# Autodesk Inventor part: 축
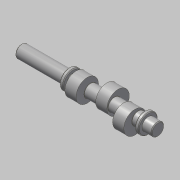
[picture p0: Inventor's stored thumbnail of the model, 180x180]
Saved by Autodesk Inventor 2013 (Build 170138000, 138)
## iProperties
Company: 한국ATC센터
Created: 2014-08
Part Number: 축
Document SubType Name: Modeling
Designer: mdu
Density: 7.86 g/cm^3
Material: 강철, 연강
Mass: 516.584 g
Surface Area: 162.516 cm^2
Volume: 65.7231 cm^3
Author: mdu
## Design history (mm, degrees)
sketch "스케치1"
  geometry: L1 (-91.5, 0)-(91.5, 0); L2 (-91.5, 0)-(-91.5, 8.5); L3 (-91.5, 8.5)-(-27.5, 8.5); L4 (-27.5, 8.5)-(-27.5, 13); L5 (-27.5, 13)-(-22.5, 13); L6 (-22.5, 13)-(-22.5, 8.5); L7 (-22.5, 8.5)-(73.5, 8.5); L8 (73.5, 8.5)-(73.5, 13); L9 (73.5, 13)-(78.5, 13); L10 (78.5, 13)-(78.5, 8.5); L11 (78.5, 8.5)-(91.5, 8.5); L12 (91.5, 8.5)-(91.5, 0); 2 further points
  constraints: 24 end point, 5 parallel, 1 coincident, 1 horizontal, 1 midpoint, 1 perpendicular
  dimensions: "d0" = 183 distance of L1.start L1.end (derived); "d2" = 17 diameter of L3 L1; "d3" = 26 diameter of L5 L1; "d4" = 17 diameter of L7 L1; "d5" = 26 diameter of L9 L1; "d6" = 17 diameter of L11 L1; "d7" = 5 distance of L8.end L9.end; "d8" = 5 distance of L4.end L5.end; "d10" = 64 distance of L2.end L3.end; "d11" = 13 distance of L10.end L11.end; "d35" = 96 distance between parallel lines of L8 L6
revolve "회전1" sketch "스케치1" stored, may be unused: angle "d12" = 90 deg
node "작업 평면7"
sketch "스케치6"
  geometry: C1 r 15 at (0, 5); 1 further point
  constraints: 1 centre point, 1 vertical alignment
  dimensions: "d37" = 30 diameter of C1; "d38" = 5 distance of C1.centre point (0, 0)
extrude "돌출4" join sketch "스케치6" stored distance "d33" = 15; taper "d34" = 0 deg
node "작업 평면8"
sketch "스케치7"
  geometry: L1 (0, 0)-(-6.5, -11.258); L2 (0, 0)-(13, 0); C1 r 15 at (-2.5, -4.33); A1 r 13 centre (0, 0) between (-6.5, -11.258) and (13, 0) reference; 1 further point
  constraints: 4 end point, 2 point on circle, 1 centre point, 1 horizontal, 1 point on line
  dimensions: "d40" = 120 deg angle of L1 L2; "d41" = 30 diameter of C1; "d42" = 5 distance of point (0, 0) C1.centre
extrude "돌출5" join sketch "스케치7" stored distance "d43" = 15; taper "d44" = 0 deg
node "작업 평면9"
sketch "스케치8"
  geometry: L1 (0, 0)-(4.25, -7.361); L2 (0, 0)-(-8.5, 0); C1 r 15 at (2.5, -4.33); A1 r 8.5 centre (0, 0) between (4.25, -7.361) and (-8.5, 0) reference; 1 further point
  constraints: 4 end point, 2 point on circle, 1 centre point, 1 horizontal, 1 point on line
  dimensions: "d46" = 120 deg angle of L1 L2; "d47" = 30 diameter of C1; "d48" = 5 distance of point (0, 0) C1.centre
extrude "돌출6" join sketch "스케치8" stored distance "d49" = 15; taper "d50" = 0 deg
node "작업 평면3"
sketch "스케치5"
  geometry: L1 (32, 8.5)-(32, -8.5) reference; L2 (27.5, -2.5)-(14.5, -2.5); L3 (14.5, 2.5)-(27.5, 2.5); A1 r 2.5 centre (14.5, 0) between (14.5, 2.5) and (14.5, -2.5); A2 r 2.5 centre (27.5, 0) between (27.5, -2.5) and (27.5, 2.5); 4 further points
  constraints: 4 end point, 4 point on circle, 4 tangent, 2 centre point, 2 point on line, 1 horizontal alignment, 1 midpoint, 1 parallel, 1 perpendicular
  dimensions: "d23" = 5 distance between parallel lines of L3 L2; "d36" = 20 dimension on A1 L1; "d52" = 2 distance edge to line of A2 L1
extrude "돌출3" cut sketch "스케치5" distance "d25" = 3; taper "d26" = 0 deg
chamfer "모따기1" distance "d27" = 1; stored, may be unused: second distance "d28" = 2, angle "d29" = 45 deg
fillet "모깎기1" dims "d51" = 0.3
chamfer "모따기2" distance "d53" = 1; stored, may be unused: second distance "d54" = 2, angle "d55" = 45 deg
node "작업 평면10"
node "솔리드1"
other parameters: "d39" = -32, "d45" = 32
